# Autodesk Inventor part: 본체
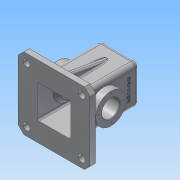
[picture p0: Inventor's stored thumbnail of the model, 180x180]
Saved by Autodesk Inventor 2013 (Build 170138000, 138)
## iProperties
Created: 2016-02
Part Number: 본체
Material: 알루미늄 6061
Document SubType Name: Modeling
Designer: Administrator
Density: 2.71 g/cm^3
Mass: 932.778 g
Surface Area: 1043.9 cm^2
Volume: 344.199 cm^3
Author: Administrator
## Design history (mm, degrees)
sketch "스케치1"
  geometry: L1 (35, -60)-(-35, -60); L2 (-35, -60)-(-35, 60); L3 (-35, 60)-(35, 60); L4 (35, 60)-(35, -60); L5 (35, -60)-(-35, 60); L6 (-35, -60)-(35, 60); 1 further point
  constraints: 12 end point, 2 midpoint, 2 parallel, 1 horizontal, 1 perpendicular
  dimensions: "d0" = 70 distance of L2.end L3.end; "d1" = 120 distance of L1.end L2.end
extrude "돌출1" new body sketch "스케치1" stored distance "d2" = 70; taper "d3" = 0 deg
feature "쉘1" dims "d4" = 5
sketch "스케치2"
  geometry: C1 r 20 at (35, 35); 1 further point
  constraints: 1 centre point, 1 coincident
  dimensions: "d5" = 40 diameter of C1
extrude "돌출2" join sketch "스케치2" distance "d6" = 10; taper "d7" = -10 deg
sketch "스케치3"
  geometry: L1 (70, 0)-(0, 0) reference; C1 r 27.5 at (35, 55); 1 further point
  constraints: 1 centre point, 1 vertical alignment
  dimensions: "d9" = 55 diameter of C1; "d10" = 55 distance from line of L1 C1.centre
extrude "돌출3" join sketch "스케치3" distance "d11" = 13; taper "d12" = 0 deg
sketch "스케치4"
  geometry: C1 r 27.5 at (30, 55) reference; C2 r 27.5 at (30, 55); 1 further point
  constraints: 1 centre point, 1 coincident
  dimensions: "d13" = 55 diameter of C2
extrude "돌출4" join sketch "스케치4" distance "d14" = 7; taper "d15" = -45 deg
sketch "스케치5"
  geometry: C1 r 27.5 at (0, 0) reference; C2 r 16 at (0, 0); 1 further point
  constraints: 1 centre point, 1 coincident
  dimensions: "d16" = 32 diameter of C2
extrude "돌출5" cut sketch "스케치5" stored distance "d17" = 7; taper "d18" = 0 deg
sketch "스케치6"
  geometry: C1 r 18.237 at (0, 0) reference; 1 further point
  constraints: 1 coincident
hole "구멍1" sketch "스케치6" at (0, 0) diameter "d19" = 21; stored, may be unused: countersink angle "d23" = 90 deg, drill point angle "d25" = 118 deg; dims "d20" = 6, "d21" = 28, "d22" = 4, "d24" = 8
sketch "스케치7"
  geometry: L1 (65, -5)-(65, -65) reference; L2 (65, -65)-(5, -65) reference; L3 (5, -65)-(5, -5) reference; L4 (5, -5)-(65, -5) reference; L5 (100, -100)-(-30, -100); L6 (-30, -100)-(-30, 30); L7 (-30, 30)-(100, 30); L8 (100, 30)-(100, -100); L9 (100, -100)-(-30, 30); L10 (-30, -100)-(100, 30); 1 further point
  constraints: 12 end point, 2 midpoint, 2 parallel, 1 horizontal, 1 perpendicular
  dimensions: "d26" = 130 distance of L6.end L7.end; "d27" = 130 distance of L5.end L6.end
extrude "돌출6" join sketch "스케치7" distance "d28" = 10; taper "d29" = 0 deg
sketch "스케치8"
  geometry: L1 (-50, 50)-(35.069, 35); L2 (-50, 35)-(60, 35) reference; L3 (-50, 65)-(-50, -65) reference; L4 (-60, 65)-(-50, 65) reference; 1 further point
  constraints: 2 end point, 2 point on line
  dimensions: "d30" = 15 distance from line of L1.start L4; "d32" = 10 deg angle of L4 L1
feature "리브1" sketch "스케치8" dims "d33" = 1, "d34" = 10, "d35" = 0, "d36" = 0, "d37" = 1, "d38" = 1
chamfer "모따기1" distance "d39" = 10; stored, may be unused: second distance "d40" = 2, angle "d41" = 45 deg
sketch "스케치9"
  geometry: L1 (90, 100)-(-20, 100) reference; L2 (100, -20)-(100, 90) reference; C1 r 6 at (-15, 85); C2 r 6 at (-15, -15); C3 r 6 at (85, -15); C4 r 6 at (85, 85); 1 further point
  constraints: 4 centre point, 2 horizontal alignment, 2 vertical alignment
  dimensions: "d42" = 12 diameter of C1; "d43" = 12 diameter of C2; "d44" = 12 diameter of C3; "d45" = 12 diameter of C4; "d46" = 100 distance of C4.centre C1.centre; "d47" = 15 distance from line of L2 C4.centre; "d48" = 100 distance of C3.centre C4.centre; "d49" = 15 distance from line of L1 C1.centre
extrude "돌출7" cut sketch "스케치9" stored distance "d50" = 10; taper "d51" = 0 deg
sketch "스케치10"
  geometry: C1 r 16 at (0, 0) reference; C2 r 27.5 at (0, 0) reference; A1 r 22.5 centre (0, 0) between (0, 22.5) and (-22.5, 0); 3 further points
  constraints: 4 point on circle, 2 vertical alignment, 1 centre point, 1 coincident, 1 horizontal alignment
  dimensions: "d52" = 45 diameter of A1
hole "구멍2" sketch "스케치10" at (0, 22.5), (-22.5, 0), (0, -22.5), (22.5, 0) diameter "d53" = 3.242; stored, may be unused: countersink angle "d57" = 90 deg, drill point angle "d59" = 118 deg; dims "d54" = 8, "d55" = 4, "d56" = 2, "d58" = 10
fillet "모깎기2" dims "d61" = 8
fillet "모깎기3" dims "d62" = 8
fillet "모깎기4" dims "d63" = 0.5
fillet "모깎기5" dims "d64" = 3
fillet "모깎기6" dims "d65" = 3
fillet "모깎기7" dims "d66" = 3
fillet "모깎기8" dims "d67" = 3
chamfer "모따기2" distance "d68" = 1; stored, may be unused: second distance "d69" = 2, angle "d70" = 45 deg
fillet "모깎기9" dims "d71" = 3
fillet "모깎기10" dims "d72" = 3
sketch "스케치11"
  geometry: L1 (8.763, 18)-(45.237, 18) reference; L2 (62, -99)-(62, 0) reference; 2 further points
  constraints: 1 other
  dimensions: "d73" = 30 distance from line of L1 point (27, -12); "d74" = 35 distance from line of point (27, -12) L2
feature "엠보싱1" sketch "스케치11" dims "d0" = 70, "d1" = 120, "d9" = 55, "d10" = 55, "d75" = 0.5, "d76" = 0
fillet "모깎기11" dims "d77" = 0.5
sketch "스케치12"
  geometry: 1 further point
node "솔리드1"
mirror "대칭1"
mirror "대칭2"
mirror "대칭3"
mirror "대칭4"
